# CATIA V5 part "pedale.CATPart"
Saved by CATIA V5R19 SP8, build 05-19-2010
Part number: pedale
Bounding box of the stored display mesh (mm): x -27.824 to 27.824, y -47 to 35.034, z -6.824 to 6.824
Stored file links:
  G:\EU_thinkMotion\CFAO_2010\SIL_groupe1\SIL_groupe1\A reprendre\scador\monocycle\pedale.CATPart
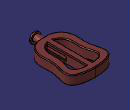
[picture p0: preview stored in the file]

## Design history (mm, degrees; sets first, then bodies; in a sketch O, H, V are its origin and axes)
Set1
  Point1: (0, 0, 0)
  Point2: (-20, -45, 0)
Body1 (main body)
  Sketch1 on xy-plane, origin (0, 0, 0), H (1, 0, 0), V (0, 1, 0)
    spline S1 through (0, -70) (-27.9315, -61.3776) (-40.1346, -33.133) (-39.5923, -3.259) (-46.3718, 43.4532) (0, 70.0682)
    spline S2 through (0, -70) (27.9315, -61.3776) (40.1346, -33.133) (39.5923, -3.259) (46.3718, 43.4532) (0, 70.0682)
    spline S3 through (-6.8034, -51.4381) (-21.6266, -35.3374) (-23.5249, -7.3644) (-26.5079, 17.8927) (-30.3044, 39.3477) (-6.8034, 53.3926)
    line L1 (-6.8034, 53.3926) -> (-6.8034, -51.4381)
    point P1 (-6.8034, 53.3926)
    point P2 (-6.8034, -51.4381)
    spline S4 through (6.8034, -51.4381) (21.6266, -35.3374) (23.5249, -7.3644) (26.5079, 17.8927) (30.3044, 39.3477) (6.8034, 53.3926)
    point P3 (6.8034, -51.4381)
    point P4 (6.8034, 53.3926)
    line L2 (6.8034, 53.3926) -> (6.8034, -51.4381)
    reference projected point E1 (0, 0) from Point1
    point P5 (0, -70)
    point P6 (0, 70.0682)
    point P7 (0, 70.0682)
    point P8 (0, -70)
    point P9 (-46.3718, 43.4532)
    point P10 (46.3718, 43.4532)
    point P11 (-39.5923, -3.259)
    point P12 (39.5923, -3.259)
    point P13 (-40.1346, -33.133)
    point P14 (40.1346, -33.133)
    point P15 (-27.9315, -61.3776)
    point P16 (27.9315, -61.3776)
    point P17 (-6.8034, 53.3926)
    point P18 (-6.8034, -51.4381)
    point P19 (6.8034, 53.3926)
    point P20 (6.8034, -51.4381)
    point P21 (-30.3044, 39.3477)
    point P22 (30.3044, 39.3477)
    point P23 (-26.5079, 17.8927)
    point P24 (26.5079, 17.8927)
    point P25 (-23.5249, -7.3644)
    point P26 (23.5249, -7.3644)
    point P27 (-21.6266, -35.3374)
    point P28 (21.6266, -35.3374)
    distance E1 P8 = 70
    coincidence: P5 V, P6 V, P17 P1, P18 P2, P5 P8, P6 P7, P20 P3, P19 P4
    symmetry: S1 S2 V, P6 P7 V, P5 P8 V, P9 P10 V, P11 P12 V, P13 P14 V, P15 P16 V, S3 S4 V, P2 P3 V, P1 P4 V, L1 L2 V, P17 P19 V, P18 P20 V, P21 P22 V, P23 P24 V, P25 P26 V, P27 P28 V
  Pad1: profile Sketch1, direction (0, 0, 1), length 8, opposite side length 8
  Affinity1: ToTransfor Pad1, AxisOrigin Point1, AxisPlane xy-plane, RatioX 0.6, RatioY 0.5, RatioZ 0.8
  Sketch2 on zx-plane, origin (0, 0, 0), H (-1, 0, 0), V (0, 0, 1)
    circle A1 centre (0, 0) radius 5
    radius A1 = 5
  Pad2: profile Sketch2, direction (0, -1, 0), length 45
  Sketch3 on end face of Pad2, origin (0, -45, 0), H (1, 0, 0), V (0, 0, 1)
    circle A1 centre (0, 0) radius 7
    reference projected circle E1 centre (0, 0) radius 5 from edge [end face of Pad2 | face of Pad2 from Sketch2.A1]
    distance A1 E1 = 2
  Pad3: profile Sketch3, direction (0, -1, 0), length 2
  Fillet1: radius 1, on start face of Pad1
  Fillet2: radius 1, on end face of Pad1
